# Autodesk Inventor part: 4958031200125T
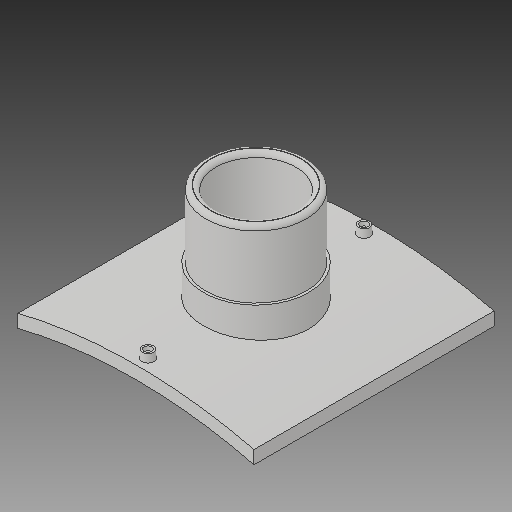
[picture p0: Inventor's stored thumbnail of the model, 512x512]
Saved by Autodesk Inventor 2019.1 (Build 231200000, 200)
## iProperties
Created: 2017-10
Part Number: 4958031200125T
Material: Generic
Description: PLASSON BRANCH SADDLE  1200x125
Document SubType Name: Modeling
Designer: KIM
Mass: 2754.05 g
Surface Area: 3037.44 cm^2
Volume: 2754.05 cm^3
Density: 1 g/cm^3
Appearance: Default
Author: KIM
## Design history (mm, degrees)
derived "495803.ipt"
feature "Solid1::495803.ipt"
tag "TaggingFeature1"
body "Solid1"
other parameters: "d1" = 16, "d2" = 295, "d4" = 0, "d12" = 625.6, "d13" = 14, "d14" = 135, "d16" = 5 deg, "d18" = 4, "d19" = 14, "d20" = 0, "d21" = 3, "d22" = 0, "d23" = 736, "d24" = 131.25, "d25" = 16, "d28" = 0, "d29" = 9.6, "d31" = 0, "d33" = 0, "d34" = 12, "d36" = 125, "d37" = 84, "d38" = 0, "d39" = 6, "d_1" = 125, "B_" = 295, "x_" = 16, "D_" = 16
